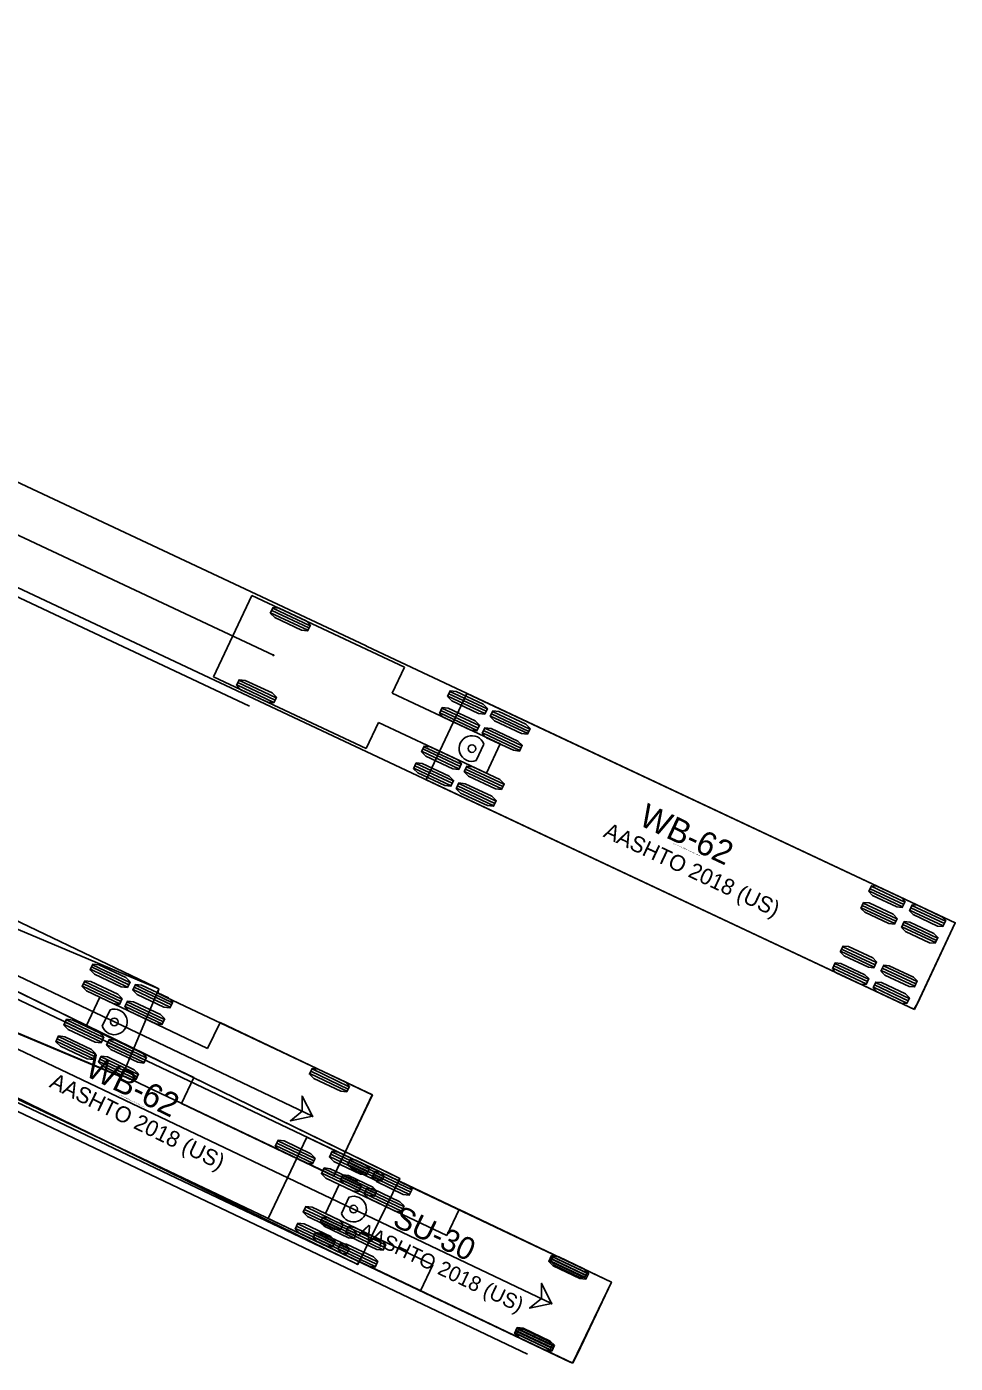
# Model space of a CAD drawing. Extents: x 186128 to 186702, y 352195 to 353183.
# Drawn here: x 186619.3 to 186701.8, y 352841.1 to 352960 of the extents above; entities that cross this region are included whole.
import ezdxf

# ---------------------------------------------------------------- set-up
doc = ezdxf.new("R2010")
doc.units = 0
doc.layers.add('SV_X_Control_Cells_Found', color=7, linetype='Continuous')
doc.layers.add('SV_X_Shot_Marker', color=7, linetype='Continuous')

msp = doc.modelspace()

# ---------------------------------------------------------------- linework, layer by layer
at = {"layer": 'SV_X_Control_Cells_Found'}
for p, q in [((186478.03, 352935.86), (186665.94, 352846.44)), ((186644.18, 352861.23), (186640.74, 352854)), ((186671.27, 352848.33), (186644.18, 352861.23)), ((186650.84, 352857.37), (186647.83, 352858.8)), ((186650.93, 352857.55), (186647.92, 352858.99)), ((186651.01, 352857.74), (186648, 352859.18)), ((186650.19, 352856.01), (186647.18, 352857.44)), ((186650.28, 352856.2), (186647.27, 352857.63)), ((186650.37, 352856.39), (186647.36, 352857.82)), ((186640.74, 352854), (186667.83, 352841.11)), ((186648.4, 352852.25), (186645.39, 352853.68)), ((186648.49, 352852.44), (186645.48, 352853.87)), ((186648.58, 352852.63), (186645.57, 352854.06)), ((186647.85, 352851.08), (186644.84, 352852.52)), ((186647.93, 352851.27), (186644.92, 352852.7)), ((186647.76, 352850.9), (186644.75, 352852.33)), ((186668.89, 352848.77), (186665.88, 352850.2)), ((186668.98, 352848.96), (186665.97, 352850.39)), ((186669.07, 352849.15), (186666.06, 352850.58)), ((186667.83, 352841.11), (186671.27, 352848.33)), ((186671.27, 352848.33), (186671.27, 352848.33)), ((186665.99, 352842.68), (186662.98, 352844.11)), ((186665.81, 352842.3), (186662.81, 352843.73)), ((186665.9, 352842.49), (186662.89, 352843.92))]:
    msp.add_line(p, q, dxfattribs=at)
for points in [[(186616.63, 352874.31), (186616.79, 352874.25), (186671.26, 352848.33), (186667.84, 352841.18), (186667.58, 352841.21), (186579.03, 352883.33), (186577.95, 352883.92), (186529.65, 352906.76), (186505.05, 352918.05), (186491.07, 352924.21)], [(186651.04, 352857.79), (186650.81, 352857.32), (186650.32, 352857.38), (186648.16, 352858.41), (186647.8, 352858.75), (186648.03, 352859.22), (186648.52, 352859.16), (186650.68, 352858.13), (186651.04, 352857.79)], [(186650.39, 352856.43), (186650.17, 352855.97), (186649.68, 352856.02), (186647.51, 352857.06), (186647.16, 352857.4), (186647.38, 352857.87), (186647.87, 352857.81), (186650.04, 352856.78), (186650.39, 352856.43)], [(186648.6, 352852.67), (186648.38, 352852.2), (186647.89, 352852.26), (186645.72, 352853.29), (186645.37, 352853.64), (186645.59, 352854.1), (186646.08, 352854.05), (186648.25, 352853.01), (186648.6, 352852.67)], [(186647.96, 352851.32), (186647.73, 352850.85), (186647.24, 352850.91), (186645.08, 352851.94), (186644.72, 352852.28), (186644.95, 352852.75), (186645.44, 352852.69), (186647.6, 352851.66), (186647.96, 352851.32)], [(186669.1, 352849.19), (186668.87, 352848.73), (186668.38, 352848.78), (186666.22, 352849.82), (186665.86, 352850.16), (186666.09, 352850.63), (186666.57, 352850.57), (186668.74, 352849.54), (186669.1, 352849.19)], [(186665.94, 352846.44), (186665.03, 352848.22), (186665.04, 352846.87), (186663.98, 352846.02), (186665.94, 352846.44)], [(186666.02, 352842.72), (186665.79, 352842.25), (186665.3, 352842.31), (186663.14, 352843.34), (186662.78, 352843.69), (186663.01, 352844.16), (186663.5, 352844.1), (186665.66, 352843.07), (186666.02, 352842.72)]]:
    msp.add_lwpolyline(points, dxfattribs=at)
msp.add_lwpolyline([(186665.94, 352846.44), (186665.03, 352848.22), (186665.04, 352846.87), (186663.98, 352846.02)], close=True, dxfattribs=at)
msp.add_circle((186665.94, 352846.44), 0.0417, dxfattribs=at)
at = {"layer": 'SV_X_Shot_Marker'}
for p, q in [((186515.24, 352963.3), (186641.2, 352904.08)), ((186517.52, 352956.7), (186639.07, 352899.56)), ((186511.01, 352926.7), (186644.66, 352863.09)), ((186526.61, 352912.75), (186665.94, 352846.44)), ((186639.28, 352909.4), (186635.88, 352902.16)), ((186652.86, 352903.02), (186639.28, 352909.4)), ((186641.14, 352908.27), (186644.46, 352906.71)), ((186640.95, 352907.86), (186644.27, 352906.3)), ((186641.05, 352908.07), (186644.36, 352906.51)), ((186530.14, 352905.53), (186663.79, 352841.93)), ((186651.76, 352900.7), (186652.86, 352903.02)), ((186635.88, 352902.16), (186649.45, 352895.78)), ((186635.88, 352902.16), (186635.88, 352902.16)), ((186637.94, 352901.45), (186641.25, 352899.89)), ((186638.03, 352901.66), (186641.35, 352900.1)), ((186638.13, 352901.86), (186641.45, 352900.3)), ((186661.36, 352896.19), (186651.76, 352900.7)), ((186658.39, 352900.69), (186654.77, 352893)), ((186656.7, 352900.45), (186660.01, 352898.89)), ((186656.79, 352900.66), (186660.11, 352899.1)), ((186656.89, 352900.87), (186660.21, 352899.31)), ((186701.83, 352880.27), (186658.39, 352900.69)), ((186655.99, 352898.96), (186659.31, 352897.4)), ((186656.09, 352899.17), (186659.41, 352897.61)), ((186656.19, 352899.38), (186659.51, 352897.82)), ((186660.59, 352898.87), (186663.91, 352897.31)), ((186660.69, 352899.08), (186664.01, 352897.52)), ((186649.45, 352895.78), (186650.54, 352898.1)), ((186650.54, 352898.1), (186660.14, 352893.59)), ((186659.99, 352897.59), (186663.31, 352896.03)), ((186660.5, 352898.67), (186663.81, 352897.11)), ((186659.79, 352897.17), (186663.11, 352895.61)), ((186659.89, 352897.38), (186663.21, 352895.82)), ((186654.38, 352895.54), (186657.7, 352893.98)), ((186654.48, 352895.75), (186657.8, 352894.18)), ((186654.58, 352895.95), (186657.9, 352894.39)), ((186659.23, 352894.71), (186659.92, 352896.17)), ((186660.14, 352893.59), (186661.36, 352896.19)), ((186653.68, 352894.04), (186657, 352892.48)), ((186653.78, 352894.25), (186657.1, 352892.69)), ((186653.88, 352894.46), (186657.19, 352892.9)), ((186658.28, 352893.96), (186661.6, 352892.4)), ((186658.38, 352894.17), (186661.7, 352892.61)), ((186631, 352874.42), (186586.76, 352893.03)), ((186654.77, 352893), (186698.21, 352872.58)), ((186654.77, 352893), (186654.77, 352893)), ((186658.18, 352893.75), (186661.5, 352892.19)), ((186657.48, 352892.26), (186660.8, 352890.7)), ((186657.58, 352892.46), (186660.9, 352890.9)), ((186657.68, 352892.67), (186661, 352891.11)), ((186583.46, 352885.19), (186627.71, 352866.58)), ((186694.26, 352883.32), (186697.25, 352881.92)), ((186694.36, 352883.53), (186697.34, 352882.13)), ((186694.16, 352883.12), (186697.15, 352881.71)), ((186693.46, 352881.62), (186696.45, 352880.22)), ((186693.56, 352881.83), (186696.54, 352880.43)), ((186693.65, 352882.04), (186696.64, 352880.63)), ((186697.78, 352881.41), (186700.77, 352880.01)), ((186697.88, 352881.62), (186700.87, 352880.22)), ((186697.98, 352881.83), (186700.96, 352880.42)), ((186697.08, 352879.92), (186700.07, 352878.52)), ((186697.18, 352880.13), (186700.16, 352878.72)), ((186697.27, 352880.34), (186700.26, 352878.93)), ((186698.21, 352872.58), (186701.83, 352880.27)), ((186652.44, 352857.54), (186609.32, 352878.61)), ((186691.64, 352877.75), (186694.62, 352876.34)), ((186691.73, 352877.95), (186694.72, 352876.55)), ((186691.83, 352878.16), (186694.82, 352876.76)), ((186628.23, 352874.57), (186624.92, 352876.15)), ((186628.33, 352874.78), (186625.02, 352876.36)), ((186628.43, 352874.99), (186625.12, 352876.56)), ((186690.94, 352876.25), (186693.92, 352874.85)), ((186691.03, 352876.46), (186694.02, 352875.06)), ((186691.13, 352876.67), (186694.12, 352875.26)), ((186695.35, 352876.25), (186698.34, 352874.85)), ((186695.45, 352876.46), (186698.44, 352875.05)), ((186627.72, 352873.5), (186624.41, 352875.07)), ((186694.75, 352874.97), (186697.74, 352873.56)), ((186695.26, 352876.04), (186698.24, 352874.64)), ((186627.53, 352873.08), (186624.21, 352874.66)), ((186627.62, 352873.29), (186624.31, 352874.87)), ((186627.71, 352866.58), (186631, 352874.42)), ((186632.03, 352872.77), (186628.72, 352874.34)), ((186632.13, 352872.98), (186628.81, 352874.55)), ((186632.22, 352873.18), (186628.91, 352874.76)), ((186631, 352874.42), (186631, 352874.42)), ((186694.56, 352874.55), (186697.54, 352873.15)), ((186694.65, 352874.76), (186697.64, 352873.35)), ((186625.77, 352873.66), (186624.54, 352871.08)), ((186635.34, 352869.11), (186625.77, 352873.66)), ((186631.32, 352871.28), (186628.01, 352872.85)), ((186631.42, 352871.49), (186628.11, 352873.06)), ((186631.52, 352871.69), (186628.2, 352873.27)), ((186626, 352869.87), (186622.69, 352871.45)), ((186626.1, 352870.08), (186622.79, 352871.66)), ((186626.67, 352872.54), (186625.98, 352871.09)), ((186636.45, 352871.43), (186635.34, 352869.11)), ((186649.99, 352864.99), (186636.45, 352871.43)), ((186605.58, 352870.97), (186648.71, 352849.9)), ((186625.9, 352869.67), (186622.59, 352871.24)), ((186624.54, 352871.08), (186634.11, 352866.52)), ((186625.19, 352868.18), (186621.88, 352869.75)), ((186625.29, 352868.38), (186621.98, 352869.96)), ((186625.39, 352868.59), (186622.08, 352870.17)), ((186629.69, 352867.86), (186626.38, 352869.44)), ((186629.79, 352868.07), (186626.48, 352869.64)), ((186629.89, 352868.28), (186626.58, 352869.85)), ((186628.98, 352866.37), (186625.67, 352867.95)), ((186629.08, 352866.58), (186625.77, 352868.15)), ((186629.18, 352866.79), (186625.87, 352868.36)), ((186647.74, 352865.3), (186644.43, 352866.87)), ((186647.84, 352865.5), (186644.53, 352867.08)), ((186647.94, 352865.71), (186644.63, 352867.29)), ((186634.11, 352866.52), (186633.01, 352864.2)), ((186646.56, 352857.76), (186649.99, 352864.99)), ((186649.99, 352864.99), (186649.99, 352864.99)), ((186633.01, 352864.2), (186646.56, 352857.76)), ((186644.8, 352859.11), (186641.49, 352860.68)), ((186644.89, 352859.31), (186641.58, 352860.89)), ((186644.7, 352858.9), (186641.39, 352860.48)), ((186649.51, 352857.93), (186646.2, 352859.5)), ((186649.61, 352858.13), (186646.3, 352859.71)), ((186649.71, 352858.34), (186646.4, 352859.91)), ((186649, 352856.85), (186645.69, 352858.42)), ((186648.81, 352856.44), (186645.49, 352858.01)), ((186648.9, 352856.64), (186645.59, 352858.22)), ((186648.71, 352849.9), (186652.44, 352857.54)), ((186653.31, 352856.12), (186650, 352857.7)), ((186653.41, 352856.33), (186650.09, 352857.9)), ((186653.5, 352856.53), (186650.19, 352858.11)), ((186652.44, 352857.54), (186652.44, 352857.54)), ((186647.05, 352857.02), (186645.82, 352854.43)), ((186656.62, 352852.46), (186647.05, 352857.02)), ((186652.6, 352854.63), (186649.29, 352856.21)), ((186652.7, 352854.84), (186649.39, 352856.41)), ((186652.79, 352855.04), (186649.48, 352856.62)), ((186647.28, 352853.23), (186643.97, 352854.8)), ((186647.38, 352853.43), (186644.07, 352855.01)), ((186647.95, 352855.9), (186647.25, 352854.44)), ((186657.73, 352854.78), (186656.62, 352852.46)), ((186671.27, 352848.33), (186657.73, 352854.78)), ((186647.18, 352853.02), (186643.87, 352854.59)), ((186645.82, 352854.43), (186655.39, 352849.87)), ((186646.47, 352851.53), (186643.16, 352853.1)), ((186646.57, 352851.74), (186643.26, 352853.31)), ((186646.67, 352851.94), (186643.36, 352853.52)), ((186650.97, 352851.21), (186647.66, 352852.79)), ((186651.07, 352851.42), (186647.76, 352853)), ((186651.17, 352851.63), (186647.86, 352853.2)), ((186650.26, 352849.72), (186646.95, 352851.3)), ((186650.36, 352849.93), (186647.05, 352851.51)), ((186650.46, 352850.14), (186647.15, 352851.71)), ((186669.02, 352848.64), (186665.71, 352850.22)), ((186669.12, 352848.85), (186665.81, 352850.43)), ((186669.22, 352849.06), (186665.9, 352850.63)), ((186655.39, 352849.87), (186654.29, 352847.56)), ((186667.83, 352841.11), (186671.27, 352848.33)), ((186671.27, 352848.33), (186671.27, 352848.33)), ((186654.29, 352847.56), (186667.83, 352841.11)), ((186666.17, 352842.66), (186662.86, 352844.24)), ((186665.97, 352842.25), (186662.66, 352843.82)), ((186666.07, 352842.45), (186662.76, 352844.03))]:
    msp.add_line(p, q, dxfattribs=at)
for points in [[(186649.38, 352904.96), (186649.54, 352904.86), (186701.84, 352880.29), (186698.49, 352873.1), (186698.16, 352872.61), (186525.1, 352954.01), (186518.86, 352957.26), (186508.96, 352961.88)], [(186534.71, 352961.62), (186538.29, 352959.03), (186544.32, 352955.16), (186548.69, 352952.7), (186553.81, 352950.01), (186564.76, 352944.69), (186649.38, 352904.96)], [(186617.33, 352874.71), (186617.49, 352874.61), (186651.78, 352857.87), (186652.43, 352857.55), (186652.33, 352857.38), (186652.4, 352857.28), (186653.45, 352856.76), (186671.26, 352848.33), (186668.25, 352841.96), (186667.85, 352841.18), (186667.75, 352841.14), (186648.92, 352850.13), (186648.79, 352850.16), (186648.69, 352849.9), (186648.46, 352850), (186607.39, 352869.55), (186562.47, 352890.72), (186536.32, 352902.82), (186516.67, 352911.71), (186513.75, 352912.86), (186506.93, 352915.22), (186484.29, 352922.74)], [(186640.92, 352907.81), (186641.17, 352908.32), (186641.71, 352908.26), (186644.1, 352907.14), (186644.49, 352906.76), (186644.24, 352906.25), (186643.71, 352906.31), (186641.32, 352907.43), (186640.92, 352907.81)], [(186637.91, 352901.4), (186638.15, 352901.91), (186638.69, 352901.85), (186641.08, 352900.73), (186641.47, 352900.35), (186641.23, 352899.84), (186640.69, 352899.9), (186638.3, 352901.02), (186637.91, 352901.4)], [(186656.67, 352900.4), (186656.91, 352900.92), (186657.45, 352900.86), (186659.84, 352899.74), (186660.23, 352899.36), (186659.99, 352898.84), (186659.45, 352898.91), (186657.06, 352900.03), (186656.67, 352900.4)], [(186655.97, 352898.91), (186656.21, 352899.43), (186656.75, 352899.37), (186659.14, 352898.24), (186659.53, 352897.87), (186659.29, 352897.35), (186658.75, 352897.41), (186656.36, 352898.54), (186655.97, 352898.91)], [(186660.47, 352898.62), (186660.72, 352899.13), (186661.25, 352899.07), (186663.64, 352897.95), (186664.03, 352897.57), (186663.79, 352897.06), (186663.25, 352897.12), (186660.86, 352898.24), (186660.47, 352898.62)], [(186659.77, 352897.12), (186660.01, 352897.64), (186660.55, 352897.58), (186662.94, 352896.45), (186663.33, 352896.08), (186663.09, 352895.56), (186662.55, 352895.63), (186660.16, 352896.75), (186659.77, 352897.12)], [(186654.36, 352895.49), (186654.6, 352896), (186655.14, 352895.94), (186657.53, 352894.82), (186657.92, 352894.44), (186657.68, 352893.93), (186657.14, 352893.99), (186654.75, 352895.11), (186654.36, 352895.49)], [(186653.66, 352893.99), (186653.9, 352894.51), (186654.44, 352894.45), (186656.83, 352893.32), (186657.22, 352892.95), (186656.98, 352892.43), (186656.44, 352892.5), (186654.05, 352893.62), (186653.66, 352893.99)], [(186658.16, 352893.7), (186658.4, 352894.22), (186658.94, 352894.15), (186661.33, 352893.03), (186661.72, 352892.66), (186661.48, 352892.14), (186660.94, 352892.2), (186658.55, 352893.32), (186658.16, 352893.7)], [(186657.46, 352892.21), (186657.7, 352892.72), (186658.24, 352892.66), (186660.63, 352891.54), (186661.02, 352891.16), (186660.78, 352890.65), (186660.24, 352890.71), (186657.85, 352891.83), (186657.46, 352892.21)], [(186614.54, 352882.3), (186630.65, 352874.59), (186631.01, 352874.4), (186630.91, 352874.03), (186631.7, 352873.64), (186650.01, 352864.98), (186646.56, 352857.79), (186628.06, 352866.59), (186627.73, 352866.69), (186627.7, 352866.55), (186627.37, 352866.69), (186577.93, 352887.45)], [(186694.14, 352883.06), (186694.38, 352883.58), (186694.87, 352883.54), (186697.02, 352882.53), (186697.37, 352882.18), (186697.12, 352881.66), (186696.63, 352881.7), (186694.48, 352882.71), (186694.14, 352883.06)], [(186693.44, 352881.57), (186693.68, 352882.09), (186694.17, 352882.05), (186696.32, 352881.04), (186696.67, 352880.68), (186696.42, 352880.17), (186695.93, 352880.21), (186693.78, 352881.22), (186693.44, 352881.57)], [(186697.76, 352881.36), (186698, 352881.88), (186698.49, 352881.84), (186700.64, 352880.83), (186700.99, 352880.48), (186700.74, 352879.96), (186700.25, 352880), (186698.1, 352881.01), (186697.76, 352881.36)], [(186697.06, 352879.87), (186697.3, 352880.39), (186697.79, 352880.35), (186699.94, 352879.34), (186700.29, 352878.98), (186700.04, 352878.46), (186699.55, 352878.51), (186697.4, 352879.52), (186697.06, 352879.87)], [(186691.61, 352877.69), (186691.86, 352878.21), (186692.35, 352878.17), (186694.5, 352877.16), (186694.84, 352876.81), (186694.6, 352876.29), (186694.11, 352876.33), (186691.96, 352877.34), (186691.61, 352877.69)], [(186628.46, 352875.04), (186628.21, 352874.52), (186627.67, 352874.59), (186625.29, 352875.72), (186624.9, 352876.1), (186625.14, 352876.61), (186625.68, 352876.55), (186628.07, 352875.42), (186628.46, 352875.04)], [(186690.91, 352876.2), (186691.15, 352876.72), (186691.65, 352876.68), (186693.8, 352875.67), (186694.14, 352875.32), (186693.9, 352874.8), (186693.41, 352874.84), (186691.26, 352875.85), (186690.91, 352876.2)], [(186695.23, 352875.99), (186695.48, 352876.51), (186695.97, 352876.47), (186698.12, 352875.46), (186698.46, 352875.11), (186698.22, 352874.59), (186697.73, 352874.63), (186695.58, 352875.64), (186695.23, 352875.99)], [(186627.75, 352873.55), (186627.5, 352873.03), (186626.96, 352873.1), (186624.58, 352874.23), (186624.19, 352874.61), (186624.44, 352875.12), (186624.97, 352875.06), (186627.36, 352873.93), (186627.75, 352873.55)], [(186694.53, 352874.5), (186694.77, 352875.02), (186695.27, 352874.98), (186697.42, 352873.97), (186697.76, 352873.61), (186697.52, 352873.1), (186697.03, 352873.14), (186694.88, 352874.15), (186694.53, 352874.5)], [(186632.25, 352873.24), (186632, 352872.72), (186631.46, 352872.78), (186629.08, 352873.92), (186628.69, 352874.29), (186628.94, 352874.81), (186629.47, 352874.75), (186631.86, 352873.61), (186632.25, 352873.24)], [(186631.54, 352871.75), (186631.29, 352871.23), (186630.76, 352871.29), (186628.37, 352872.43), (186627.98, 352872.8), (186628.23, 352873.32), (186628.77, 352873.26), (186631.15, 352872.12), (186631.54, 352871.75)], [(186626.12, 352870.13), (186625.88, 352869.62), (186625.34, 352869.68), (186622.95, 352870.81), (186622.56, 352871.19), (186622.81, 352871.71), (186623.35, 352871.64), (186625.73, 352870.51), (186626.12, 352870.13)], [(186625.41, 352868.64), (186625.17, 352868.13), (186624.63, 352868.19), (186622.25, 352869.32), (186621.86, 352869.7), (186622.1, 352870.22), (186622.64, 352870.15), (186625.02, 352869.02), (186625.41, 352868.64)], [(186629.91, 352868.33), (186629.67, 352867.81), (186629.13, 352867.88), (186626.75, 352869.01), (186626.36, 352869.39), (186626.6, 352869.9), (186627.14, 352869.84), (186629.52, 352868.7), (186629.91, 352868.33)], [(186629.21, 352866.84), (186628.96, 352866.32), (186628.42, 352866.39), (186626.04, 352867.52), (186625.65, 352867.9), (186625.89, 352868.41), (186626.43, 352868.35), (186628.82, 352867.21), (186629.21, 352866.84)], [(186647.96, 352865.76), (186647.72, 352865.25), (186647.18, 352865.31), (186644.79, 352866.44), (186644.4, 352866.82), (186644.65, 352867.34), (186645.19, 352867.27), (186647.57, 352866.14), (186647.96, 352865.76)], [(186644.66, 352863.09), (186643.75, 352864.87), (186643.76, 352863.52), (186642.71, 352862.68), (186644.66, 352863.09)], [(186644.92, 352859.36), (186644.67, 352858.85), (186644.14, 352858.91), (186641.75, 352860.05), (186641.36, 352860.42), (186641.61, 352860.94), (186642.15, 352860.88), (186644.53, 352859.74), (186644.92, 352859.36)], [(186649.74, 352858.39), (186649.49, 352857.87), (186648.95, 352857.94), (186646.57, 352859.07), (186646.18, 352859.45), (186646.42, 352859.97), (186646.96, 352859.9), (186649.35, 352858.77), (186649.74, 352858.39)], [(186649.03, 352856.9), (186648.78, 352856.38), (186648.24, 352856.45), (186645.86, 352857.58), (186645.47, 352857.96), (186645.72, 352858.48), (186646.25, 352858.41), (186648.64, 352857.28), (186649.03, 352856.9)], [(186653.53, 352856.59), (186653.28, 352856.07), (186652.74, 352856.13), (186650.36, 352857.27), (186649.97, 352857.64), (186650.22, 352858.16), (186650.75, 352858.1), (186653.14, 352856.96), (186653.53, 352856.59)], [(186652.82, 352855.1), (186652.57, 352854.58), (186652.04, 352854.64), (186649.65, 352855.78), (186649.26, 352856.15), (186649.51, 352856.67), (186650.05, 352856.61), (186652.43, 352855.47), (186652.82, 352855.1)], [(186647.4, 352853.48), (186647.15, 352852.97), (186646.62, 352853.03), (186644.23, 352854.17), (186643.84, 352854.54), (186644.09, 352855.06), (186644.63, 352854.99), (186647.01, 352853.86), (186647.4, 352853.48)], [(186646.69, 352851.99), (186646.45, 352851.48), (186645.91, 352851.54), (186643.52, 352852.68), (186643.14, 352853.05), (186643.38, 352853.57), (186643.92, 352853.51), (186646.3, 352852.37), (186646.69, 352851.99)], [(186651.19, 352851.68), (186650.95, 352851.16), (186650.41, 352851.23), (186648.03, 352852.36), (186647.64, 352852.74), (186647.88, 352853.26), (186648.42, 352853.19), (186650.8, 352852.06), (186651.19, 352851.68)], [(186650.48, 352850.19), (186650.24, 352849.67), (186649.7, 352849.74), (186647.32, 352850.87), (186646.93, 352851.25), (186647.17, 352851.77), (186647.71, 352851.7), (186650.09, 352850.57), (186650.48, 352850.19)], [(186669.24, 352849.11), (186668.99, 352848.59), (186668.46, 352848.66), (186666.07, 352849.79), (186665.68, 352850.17), (186665.93, 352850.68), (186666.47, 352850.62), (186668.85, 352849.49), (186669.24, 352849.11)], [(186665.94, 352846.44), (186665.03, 352848.22), (186665.04, 352846.87), (186663.98, 352846.02), (186665.94, 352846.44)], [(186666.2, 352842.71), (186665.95, 352842.2), (186665.41, 352842.26), (186663.03, 352843.4), (186662.64, 352843.77), (186662.88, 352844.29), (186663.42, 352844.22), (186665.81, 352843.09), (186666.2, 352842.71)]]:
    msp.add_lwpolyline(points, dxfattribs=at)
for points in [[(186644.66, 352863.09), (186643.75, 352864.87), (186643.76, 352863.52), (186642.71, 352862.68)], [(186665.94, 352846.44), (186665.03, 352848.22), (186665.04, 352846.87), (186663.98, 352846.02)]]:
    msp.add_lwpolyline(points, close=True, dxfattribs=at)
for centre, radius in [((186641.2, 352904.08), 0.0417), ((186658.85, 352895.78), 0.34), ((186627.05, 352871.47), 0.34), ((186644.66, 352863.09), 0.0417), ((186648.33, 352854.82), 0.34), ((186665.94, 352846.44), 0.0417)]:
    msp.add_circle(centre, radius, dxfattribs=at)
for centre, start, end in [((186658.85, 352895.78), 19.8189, 289.8189), ((186627.05, 352871.47), 199.5651, 109.5651), ((186648.33, 352854.82), 199.5513, 109.5513)]:
    msp.add_arc(centre, 1.14, start, end, dxfattribs=at)

# ---------------------------------------------------------------- texts
at = {"layer": 'SV_X_Control_Cells_Found'}
for s, height, p in [('SU-30', 2, (186651.69, 352853.4)), ('AASHTO 2018 (US)', 1.3333, (186648.63, 352852.46)), ('(c) 2025 Transoft Solutions, Inc. All rights reserved.', 0.08, (186654.51, 352851.84))]:
    msp.add_text(s, height=height, rotation=334.5494, dxfattribs=at).set_placement(p)
at = {"layer": 'SV_X_Shot_Marker'}
for s, height, rotation, p in [('WB-62', 2.125, 334.8189, (186673.57, 352889.05)), ('AASHTO 2018 (US)', 1.4167, 334.8189, (186670.46, 352887.97)), ('(c) 2025 Transoft Solutions, Inc. All rights reserved.', 0.085, 334.8189, (186676.71, 352887.34)), ('WB-62', 2.125, 333.9609, (186624.32, 352866.74)), ('AASHTO 2018 (US)', 1.4167, 333.9609, (186621.19, 352865.71)), ('(c) 2025 Transoft Solutions, Inc. All rights reserved.', 0.085, 333.9609, (186627.43, 352864.98))]:
    msp.add_text(s, height=height, rotation=rotation, dxfattribs=at).set_placement(p)

doc.saveas('drawing.dxf')
